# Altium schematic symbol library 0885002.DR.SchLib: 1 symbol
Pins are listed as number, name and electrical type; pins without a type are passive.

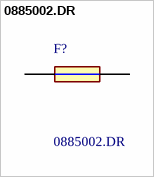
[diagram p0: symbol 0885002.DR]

## 0885002.DR
designator F?
FUSE 500V HBC NANO2 PB-FREE 2A; Manufacturer_Name: LITTELFUSE; Geometry.Height: 4.88mm
footprint FUSC10948X488N
pins: 1, 2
